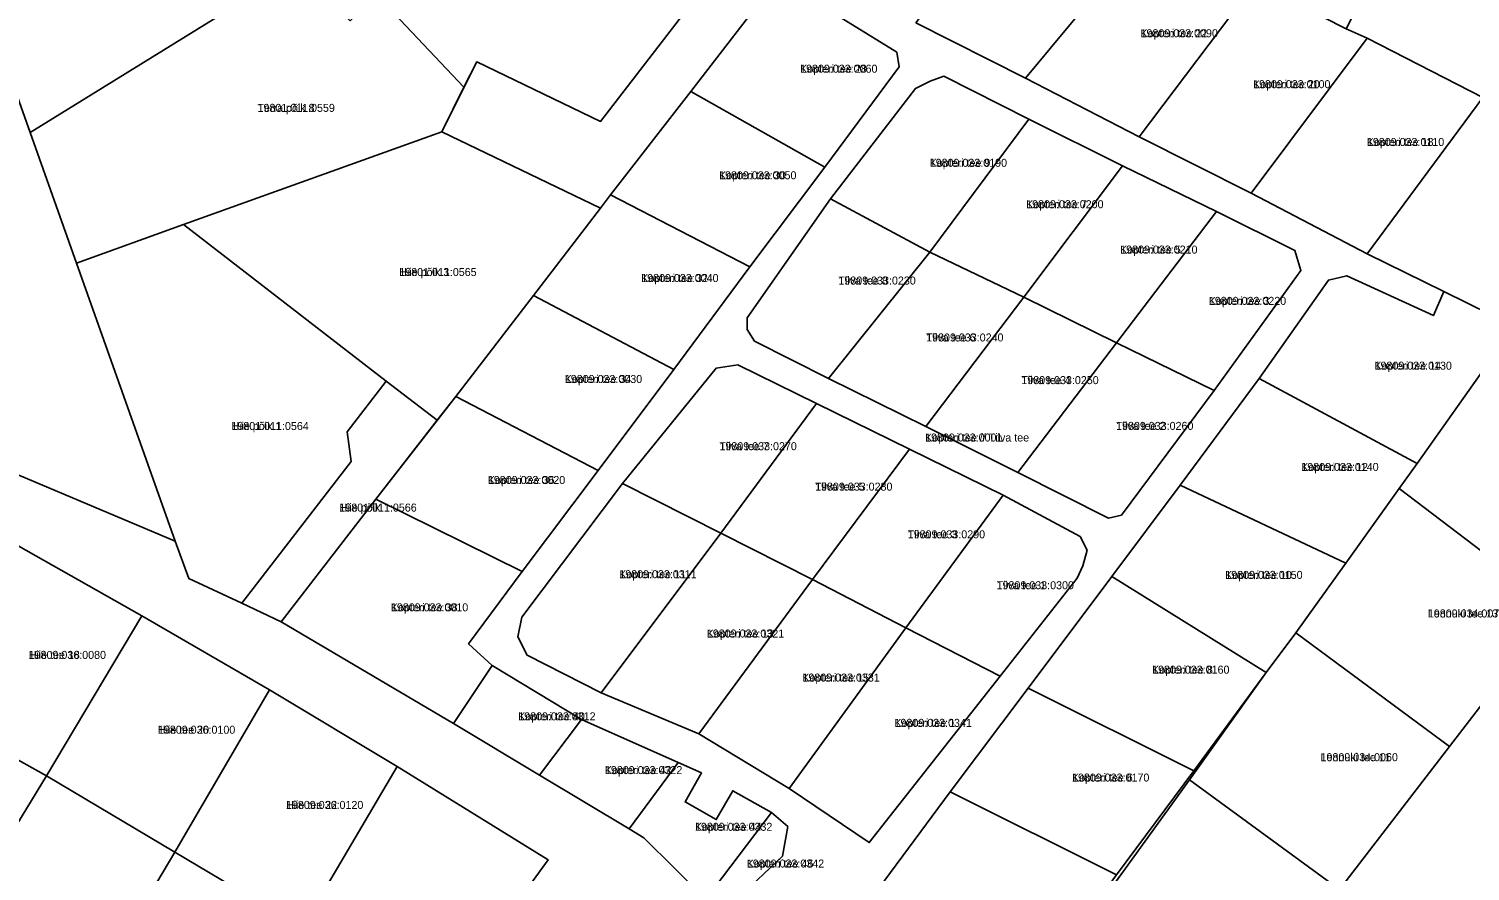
# Model space of a CAD drawing. Extents: x 516875 to 535633, y 6574491 to 6593094.
# Drawn here: x 521221.7 to 521492, y 6588153.3 to 6588311.2 of the extents above; entities that cross this region are included whole.
import ezdxf

# ---------------------------------------------------------------- set-up
doc = ezdxf.new("R2010")
doc.units = 0
for name, color, linetype in [('L_AADRESS', 7, 'Continuous'), ('PIIR', 7, 'Continuous'), ('TUNNUS', 7, 'Continuous')]:
    doc.layers.add(name, color=color, linetype=linetype)

msp = doc.modelspace()

# ---------------------------------------------------------------- linework, layer by layer
at = {"layer": 'PIIR'}
for points in [[(521244.09, 6588355.92), (521274.1, 6588324.03), (521221.98, 6588291.81), (521212.99, 6588317.04), (521208.96, 6588319.99)], [(521318.72, 6588351.51), (521355.48, 6588328.35), (521328.95, 6588293.9), (521305.71, 6588305.06), (521303.32, 6588300.29), (521287.06, 6588317.56), (521290.7, 6588320.99), (521282.78, 6588329.4)], [(521468.72, 6588311.25), (521486.78, 6588346.95), (521509.89, 6588335.14), (521515.92, 6588287.13), (521494.35, 6588298.36), (521472.65, 6588309.47)], [(521388.06, 6588312.36), (521409.79, 6588340.96), (521411.59, 6588340.18), (521431.72, 6588329.86), (521408.61, 6588301.99)], [(521408.61, 6588301.99), (521431.72, 6588329.86), (521440.11, 6588325.68), (521451.74, 6588319.93), (521429.91, 6588290.99)], [(521274.1, 6588324.03), (521273.74, 6588321.5), (521281.96, 6588312.77), (521287.06, 6588317.56), (521303.32, 6588300.29), (521299.15, 6588291.94), (521250.77, 6588274.53), (521230.7, 6588267.32), (521221.98, 6588291.81)], [(521384.51, 6588306.87), (521384.95, 6588304.15), (521371, 6588285.34), (521345.87, 6588299.49), (521362.2, 6588320.69)], [(521429.91, 6588290.99), (521451.74, 6588319.93), (521468.72, 6588311.25), (521472.65, 6588309.47), (521450.9, 6588280.42)], [(521249.19, 6588215.21), (521164, 6588251.13), (521212.99, 6588317.04), (521221.98, 6588291.81), (521230.7, 6588267.32)], [(521450.9, 6588280.42), (521472.65, 6588309.47), (521494.35, 6588298.36), (521472.7, 6588269.08)], [(521390.75, 6588301.45), (521387.97, 6588300.08), (521372.08, 6588279.39), (521356.4, 6588257.08), (521356.42, 6588254.87), (521357.77, 6588252.7), (521371.69, 6588245.71), (521389.95, 6588236.71), (521407.19, 6588228.06), (521424.15, 6588219.52), (521426.6, 6588220.08), (521443.99, 6588243.41), (521460.25, 6588265.95), (521459.11, 6588269.67), (521444.43, 6588276.98), (521426.82, 6588285.58), (521409.22, 6588294.3), (521393.32, 6588302.35)], [(521390.75, 6588301.45), (521393.32, 6588302.35), (521409.22, 6588294.3), (521390.66, 6588269.35), (521372.08, 6588279.39), (521387.97, 6588300.08)], [(521371, 6588285.34), (521356.95, 6588266.6), (521330.78, 6588280.14), (521345.87, 6588299.49)], [(521472.7, 6588269.08), (521494.35, 6588298.36), (521515.92, 6588287.13), (521521.59, 6588284.3), (521513.98, 6588274.11), (521500.26, 6588255.51), (521487.06, 6588261.98)], [(521426.82, 6588285.58), (521408.28, 6588260.96), (521390.66, 6588269.35), (521409.22, 6588294.3)], [(521288.76, 6588245.21), (521250.77, 6588274.53), (521299.15, 6588291.94), (521328.95, 6588277.65), (521316.35, 6588261.26), (521301.79, 6588242.3), (521298.28, 6588237.85)], [(521444.43, 6588276.98), (521425.7, 6588252.4), (521408.28, 6588260.96), (521426.82, 6588285.58)], [(521356.95, 6588266.6), (521342.65, 6588247.39), (521316.35, 6588261.26), (521328.95, 6588277.65), (521330.78, 6588280.14)], [(521390.66, 6588269.35), (521371.69, 6588245.71), (521357.77, 6588252.7), (521356.42, 6588254.87), (521356.4, 6588257.08), (521372.08, 6588279.39)], [(521288.76, 6588245.21), (521281.43, 6588235.71), (521282.15, 6588230.1), (521261.65, 6588203.54), (521251.74, 6588208.19), (521249.19, 6588215.21), (521230.7, 6588267.32), (521250.77, 6588274.53)], [(521459.11, 6588269.67), (521460.25, 6588265.95), (521443.99, 6588243.41), (521425.7, 6588252.4), (521444.43, 6588276.98)], [(521408.28, 6588260.96), (521389.95, 6588236.71), (521371.69, 6588245.71), (521390.66, 6588269.35)], [(521468.83, 6588264.96), (521485.1, 6588257.47), (521487.06, 6588261.98), (521500.26, 6588255.51), (521497.45, 6588251.53), (521482.03, 6588229.72), (521452.44, 6588245.67), (521465.41, 6588264.13)], [(521342.65, 6588247.39), (521328.5, 6588228.42), (521301.79, 6588242.3), (521316.35, 6588261.26)], [(521425.7, 6588252.4), (521407.19, 6588228.06), (521389.95, 6588236.71), (521408.28, 6588260.96)], [(521443.99, 6588243.41), (521426.6, 6588220.08), (521424.15, 6588219.52), (521407.19, 6588228.06), (521425.7, 6588252.4)], [(521523.86, 6588230.58), (521526.64, 6588226.06), (521508.12, 6588202.69), (521478.66, 6588225.07), (521482.03, 6588229.72), (521497.45, 6588251.53)], [(521354.65, 6588248.24), (521350.61, 6588247.6), (521333.04, 6588225.98), (521314.16, 6588200.94), (521313.44, 6588197.22), (521315.17, 6588193.8), (521329.06, 6588186.74), (521347.37, 6588179.05), (521364.28, 6588168.83), (521379.3, 6588158.67), (521403.83, 6588189.86), (521418.28, 6588208.24), (521419.37, 6588210.53), (521420.19, 6588213.5), (521418.84, 6588216.06), (521404.41, 6588223.81), (521386.85, 6588232.44), (521369.42, 6588241)], [(521354.65, 6588248.24), (521369.42, 6588241), (521351.47, 6588216.67), (521333.04, 6588225.98), (521350.61, 6588247.6)], [(521288.76, 6588245.21), (521298.28, 6588237.85), (521286.83, 6588223.08), (521269.05, 6588200.08), (521261.65, 6588203.54), (521282.15, 6588230.1), (521281.43, 6588235.71)], [(521482.03, 6588229.72), (521478.66, 6588225.07), (521468.66, 6588211.03), (521437.62, 6588225.66), (521452.44, 6588245.67)], [(521328.5, 6588228.42), (521314.21, 6588209.49), (521286.83, 6588223.08), (521301.79, 6588242.3)], [(521386.85, 6588232.44), (521368.65, 6588207.99), (521351.47, 6588216.67), (521369.42, 6588241)], [(521404.41, 6588223.81), (521386.19, 6588198.96), (521368.65, 6588207.99), (521386.85, 6588232.44)], [(521351.47, 6588216.67), (521329.06, 6588186.74), (521315.17, 6588193.8), (521313.44, 6588197.22), (521314.16, 6588200.94), (521333.04, 6588225.98)], [(521468.66, 6588211.03), (521459.29, 6588197.98), (521453.71, 6588190.56), (521424.8, 6588208.58), (521437.62, 6588225.66)], [(521314.21, 6588209.49), (521304.2, 6588195.93), (521308.63, 6588191.88), (521301.38, 6588180.99), (521269.05, 6588200.08), (521286.83, 6588223.08)], [(521418.84, 6588216.06), (521420.19, 6588213.5), (521419.37, 6588210.53), (521418.28, 6588208.24), (521403.83, 6588189.86), (521386.19, 6588198.96), (521404.41, 6588223.81)], [(521508.12, 6588202.69), (521488.12, 6588176.69), (521459.29, 6588197.98), (521468.66, 6588211.03), (521478.66, 6588225.07)], [(521242.95, 6588201.16), (521225.06, 6588171.18), (521200.48, 6588184.86), (521217.86, 6588215.37)], [(521368.65, 6588207.99), (521347.37, 6588179.05), (521329.06, 6588186.74), (521351.47, 6588216.67)], [(521386.19, 6588198.96), (521364.28, 6588168.83), (521347.37, 6588179.05), (521368.65, 6588207.99)], [(521453.71, 6588190.56), (521440.2, 6588172.11), (521409.1, 6588187.6), (521424.8, 6588208.58)], [(521266.84, 6588187.34), (521249.1, 6588156.87), (521225.06, 6588171.18), (521242.95, 6588201.16)], [(521403.83, 6588189.86), (521379.3, 6588158.67), (521364.28, 6588168.83), (521386.19, 6588198.96)], [(521488.12, 6588176.69), (521467.47, 6588149.88), (521439.37, 6588170.42), (521453.71, 6588190.56), (521459.29, 6588197.98)], [(521325.34, 6588181.77), (521317.52, 6588171.31), (521301.38, 6588180.99), (521308.63, 6588191.88)], [(521290.81, 6588172.96), (521273.02, 6588142.68), (521249.1, 6588156.87), (521266.84, 6588187.34)], [(521440.2, 6588172.11), (521425.69, 6588152.61), (521394.5, 6588168.18), (521409.1, 6588187.6)], [(521225.06, 6588171.18), (521206.39, 6588140.55), (521193.2, 6588147.93), (521182.66, 6588154.14), (521196.1, 6588177.62), (521200.48, 6588184.86)], [(521343.47, 6588173.7), (521334.28, 6588161.25), (521317.52, 6588171.31), (521325.34, 6588181.77)], [(521319.09, 6588155.45), (521298.75, 6588127.37), (521273.02, 6588142.68), (521290.81, 6588172.96)], [(521347.85, 6588171.73), (521344.77, 6588166.29), (521350.63, 6588162.97), (521353.71, 6588168.4), (521360.97, 6588164.28), (521348.67, 6588148.07), (521337.07, 6588159.57), (521334.28, 6588161.25), (521343.47, 6588173.7)], [(521249.1, 6588156.87), (521231.05, 6588126.44), (521206.39, 6588140.55), (521225.06, 6588171.18)], [(521467.47, 6588149.88), (521445.49, 6588122.56), (521443.81, 6588124.01), (521418.19, 6588141.14), (521439.37, 6588170.42)], [(521425.69, 6588152.61), (521408, 6588128.54), (521378.45, 6588146.05), (521378.85, 6588147.09), (521394.5, 6588168.18)], [(521364.05, 6588161.68), (521363.04, 6588156.13), (521354.89, 6588148.37), (521351.93, 6588144.84), (521348.67, 6588148.07), (521360.97, 6588164.28)], [(521273.02, 6588142.68), (521255.39, 6588112.43), (521231.05, 6588126.44), (521249.1, 6588156.87)]]:
    msp.add_lwpolyline(points, close=True, dxfattribs=at)
for points in [[(521354.89, 6588148.37), (521363.04, 6588156.13), (521364.05, 6588161.68), (521360.97, 6588164.28), (521353.71, 6588168.4), (521350.63, 6588162.97), (521344.77, 6588166.29), (521347.85, 6588171.73), (521343.47, 6588173.7), (521325.34, 6588181.77), (521308.63, 6588191.88), (521304.2, 6588195.93), (521314.21, 6588209.49), (521328.5, 6588228.42), (521342.65, 6588247.39), (521356.95, 6588266.6), (521371, 6588285.34), (521384.95, 6588304.15), (521384.51, 6588306.87), (521362.2, 6588320.69), (521345.87, 6588299.49), (521330.78, 6588280.14), (521328.95, 6588277.65), (521299.15, 6588291.94), (521305.71, 6588305.06), (521328.95, 6588293.9), (521355.48, 6588328.35)], [(521017.6, 6588315.56), (521041.3, 6588310.85), (521161.97, 6588248.41), (521164, 6588251.13), (521249.19, 6588215.21), (521251.74, 6588208.19), (521261.65, 6588203.54), (521269.05, 6588200.08), (521301.38, 6588180.99), (521317.52, 6588171.31), (521334.28, 6588161.25), (521337.07, 6588159.57), (521348.67, 6588148.07), (521351.93, 6588144.84), (521356.73, 6588139.38), (521385.64, 6588111.65), (521391.55, 6588105.98), (521409.24, 6588092.16), (521430.76, 6588073.85), (521450.73, 6588055.41), (521470.18, 6588036.92), (521476.73, 6588029.86), (521486.21, 6588020.09), (521519.33, 6587984.61)], [(521388.06, 6588312.36), (521408.61, 6588301.99), (521429.91, 6588290.99), (521450.9, 6588280.42), (521472.7, 6588269.08), (521487.06, 6588261.98), (521485.1, 6588257.47), (521468.83, 6588264.96), (521465.41, 6588264.13), (521452.44, 6588245.67), (521437.62, 6588225.66), (521424.8, 6588208.58), (521409.1, 6588187.6), (521394.5, 6588168.18), (521378.85, 6588147.09)], [(521158.93, 6587943.85), (521180.61, 6587971.98), (521193.57, 6587989.19), (521210.46, 6588011.39), (521226.67, 6588031.69), (521243.16, 6588051), (521258.36, 6588070.34), (521275.91, 6588092.39), (521278.32, 6588099.31), (521298.75, 6588127.37), (521319.09, 6588155.45), (521290.81, 6588172.96), (521266.84, 6588187.34), (521242.95, 6588201.16), (521217.86, 6588215.37), (521191.59, 6588226.05), (521158.76, 6588238.82), (521154.23, 6588241.17), (521121.69, 6588257.97), (521102.37, 6588267.78), (521050.16, 6588294.72), (521045.07, 6588297.27), (521040.82, 6588299.53), (521002.53, 6588304.56)], [(521540.83, 6588089.77), (521489.11, 6588041.31), (521476.73, 6588029.86), (521470.18, 6588036.92), (521500.13, 6588065.78), (521478.34, 6588084.96), (521458.19, 6588103.05), (521439.62, 6588119.88), (521443.81, 6588124.01), (521445.49, 6588122.56), (521467.47, 6588149.88), (521488.12, 6588176.69), (521508.12, 6588202.69)]]:
    msp.add_lwpolyline(points, dxfattribs=at)

# ---------------------------------------------------------------- texts
at = {"layer": 'L_AADRESS'}
for s, p in [('Kopteri tee 22', (521430.18, 6588309.67)), ('Kopteri tee 28', (521366.35, 6588303.02)), ('Kopteri tee 20', (521451.28, 6588300.12)), ('Terra põik 8', (521264.62, 6588295.68)), ('Kopteri tee 18', (521472.62, 6588289.28)), ('Kopteri tee 9', (521390.65, 6588285.38)), ('Kopteri tee 30', (521351.16, 6588283.04)), ('Kopteri tee 7', (521408.74, 6588277.61)), ('Kopteri tee 5', (521426.36, 6588269.11)), ('Hiie põik 3', (521291.2, 6588264.9)), ('Kopteri tee 32', (521336.56, 6588263.77)), ('Tiiva tee 8', (521373.53, 6588263.3)), ('Kopteri tee 3', (521442.98, 6588259.49)), ('Tiiva tee 6', (521389.98, 6588252.63)), ('Kopteri tee 14', (521474.05, 6588247.34)), ('Kopteri tee 34', (521322.24, 6588244.84)), ('Tiiva tee 4', (521407.83, 6588244.63)), ('Hiie põik 1', (521259.73, 6588236.03)), ('Tiiva tee 2', (521425.59, 6588236.05)), ('Tiiva tee 7', (521351.23, 6588232.24)), ('Kopteri tee // Tiiva tee', (521389.78, 6588233.87)), ('Kopteri tee 12', (521460.32, 6588228.35)), ('Kopteri tee 36', (521307.81, 6588225.9)), ('Tiiva tee 5', (521369.16, 6588224.66)), ('Hiie põik', (521279.96, 6588220.73)), ('Tiiva tee 3', (521386.53, 6588215.72)), ('Kopteri tee 11', (521332.45, 6588208.24)), ('Kopteri tee 10', (521446.06, 6588208.11)), ('Tiiva tee 1', (521403.19, 6588206.17)), ('Kopteri tee 38', (521289.63, 6588202.03)), ('Lennuki tee 13', (521484.05, 6588200.88)), ('Kopteri tee 13', (521348.86, 6588197.12)), ('Hiie tee 18', (521221.71, 6588193.11)), ('Kopteri tee 8', (521432.35, 6588190.34)), ('Kopteri tee 15', (521366.78, 6588188.86)), ('Kopteri tee 40', (521313.5, 6588181.59)), ('Hiie tee 20', (521245.95, 6588179.08)), ('Kopteri tee 1', (521384.05, 6588180.37)), ('Lennuki tee 11', (521463.93, 6588173.93)), ('Kopteri tee 42', (521329.76, 6588171.51)), ('Kopteri tee 6', (521417.33, 6588170.11)), ('Hiie tee 22', (521269.96, 6588164.98)), ('Kopteri tee 44', (521346.64, 6588160.88)), ('Kopteri tee 46', (521356.36, 6588153.99))]:
    msp.add_text(s, height=1.5, dxfattribs=at).set_placement(p)
at = {"layer": 'TUNNUS'}
for s, p in [('19809:033:0090', (521430.18, 6588309.67)), ('19809:033:0060', (521366.35, 6588303.02)), ('19809:033:0100', (521451.28, 6588300.12)), ('19801:011:0559', (521264.62, 6588295.68)), ('19809:033:0110', (521472.62, 6588289.28)), ('19809:033:0190', (521390.65, 6588285.38)), ('19809:033:0050', (521351.16, 6588283.04)), ('19809:033:0200', (521408.74, 6588277.61)), ('19809:033:0210', (521426.36, 6588269.11)), ('19801:011:0565', (521291.2, 6588264.9)), ('19809:033:0040', (521336.56, 6588263.77)), ('19809:033:0230', (521373.53, 6588263.3)), ('19809:033:0220', (521442.98, 6588259.49)), ('19809:033:0240', (521389.98, 6588252.63)), ('19809:033:0130', (521474.05, 6588247.34)), ('19809:033:0030', (521322.24, 6588244.84)), ('19809:033:0250', (521407.83, 6588244.63)), ('19801:011:0564', (521259.73, 6588236.03)), ('19809:033:0260', (521425.59, 6588236.05)), ('19809:033:0270', (521351.23, 6588232.24)), ('19809:033:0001', (521389.78, 6588233.87)), ('19809:033:0140', (521460.32, 6588228.35)), ('19809:033:0020', (521307.81, 6588225.9)), ('19809:033:0280', (521369.16, 6588224.66)), ('19801:011:0566', (521279.96, 6588220.73)), ('19809:033:0290', (521386.53, 6588215.72)), ('19809:033:0311', (521332.45, 6588208.24)), ('19809:033:0150', (521446.06, 6588208.11)), ('19809:033:0300', (521403.19, 6588206.17)), ('19809:033:0010', (521289.63, 6588202.03)), ('19809:034:0070', (521484.05, 6588200.88)), ('19809:033:0321', (521348.86, 6588197.12)), ('19809:036:0080', (521221.71, 6588193.11)), ('19809:033:0160', (521432.35, 6588190.34)), ('19809:033:0331', (521366.78, 6588188.86)), ('19809:033:0312', (521313.5, 6588181.59)), ('19809:036:0100', (521245.95, 6588179.08)), ('19809:033:0341', (521384.05, 6588180.37)), ('19809:034:0060', (521463.93, 6588173.93)), ('19809:033:0322', (521329.76, 6588171.51)), ('19809:033:0170', (521417.33, 6588170.11)), ('19809:036:0120', (521269.96, 6588164.98)), ('19809:033:0332', (521346.64, 6588160.88)), ('19809:033:0342', (521356.36, 6588153.99))]:
    msp.add_text(s, height=1.5, dxfattribs=at).set_placement(p)

doc.saveas('drawing.dxf')
